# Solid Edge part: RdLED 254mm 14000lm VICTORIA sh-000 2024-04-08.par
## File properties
Author: robert.pupel
Template: iso metric part.par
Last saved by: robert.pupel
Revision: 3
Application: Solid Edge
Gęstość: 0.000 kg/m^3
Dokładność: 0.990
Username: robert.pupel
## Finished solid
Body 1: solid body, 5714 faces, 14913 edges, 9879 vertices.
  Faces by surface: plane 5459, cylinder 126, torus 52, cone 44, spline 23, sphere 10
  Edges by curve: line 14360, curve on surface 311, circle 145, ellipse 66, spline 31
Bounding box of the edges (mm; curved faces can reach further): 254.000 x 4.950 x 254.000, from (-127, -3.45, -127) to (127, 1.5, 127).
Cylindrical faces by radius (mm): R0.199 x1, R0.2 x39, R0.2002 x2, R0.2169 x3, R0.25 x12, R0.3 x2, R0.3373 x3, R0.4 x8, R0.4006 x2, R0.4008 x2, R0.525 x2, R0.6 x12, R1 x7, R1.0894 x2, R1.0991 x4, R1.1 x14, R1.6 x3, R1.65 x3, R5 x4, R127 x1
Conical faces (half-angle, radius in mm at the cone's reference point): 0.3913 deg R1.0968 x2, 0.447 deg R1.0952 x2, 0.464 deg R1.0955 x2, 0.5 deg R0.5056 x4, 0.5 deg R1.0082 x4, 1 deg R0.5511 x2, 10 deg R0.2132 x2, 10 deg R0.4132 x2, 15.6748 deg R1.1041 x1, 15.6751 deg R1.1041 x1, 15.7937 deg R1.1267 x1, 15.7938 deg R1.1267 x1, 18.4844 deg R1.0657 x4, 18.9316 deg R0.5099 x2, 19.4337 deg R0.5111 x2, 27.363 deg R0.6214 x2, 40.1968 deg R0.519 x1, 40.228 deg R0.5176 x1, 42.9179 deg R0.4919 x1, 42.9331 deg R0.4916 x1, 45 deg R0.575 x2, 45 deg R0.625 x4
Toroidal faces (ring radius, tube radius in mm): R0.0958 r0.3997 x4, R0.1 r0.2 x1, R0.1075 r0.4 x2, R0.1101 r0.4001 x2, R0.1216 r0.4 x2, R0.1234 r0.4 x2, R0.1634 r0.2287 x1, R0.1641 r0.2287 x1, R0.3286 r0.2001 x1, R0.3702 r0.4 x2, R0.3818 r0.2 x2, R0.4163 r0.3984 x2, R0.4824 r0.2001 x1, R0.4952 r0.2 x1, R0.6008 r0.3968 x2, R0.6009 r0.3969 x2, R0.6227 r0.2 x1, R0.6235 r0.2 x1, R0.8 r0.2 x4, R0.8522 r0.3 x2, R0.9002 r0.2 x1, R0.9018 r0.2 x1, R0.9181 r0.2227 x2, R0.9197 r0.223 x1, R0.9199 r0.223 x1, R0.9663 r0.2263 x1, R0.9665 r0.2263 x1, R1.3 r0.2 x2, R1.327 r1.1 x2, R1.3271 r1.1 x2, R1.8741 r0.2175 x1, R1.8987 r0.2 x1
Spherical faces by radius (mm): R0.2 x8, R0.6 x2
Planar faces by outward normal: +x 652, +y 8, +z 658, -x 652, -y 1028, -z 649, oblique 1812
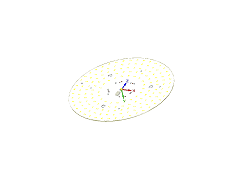
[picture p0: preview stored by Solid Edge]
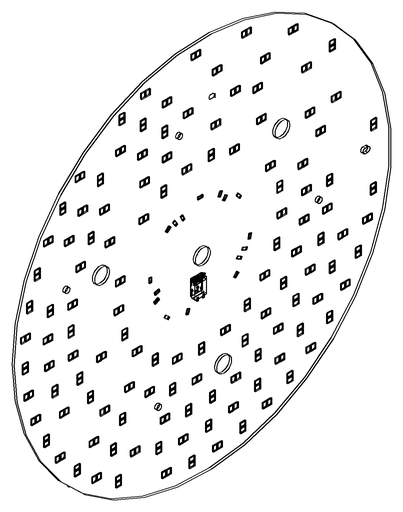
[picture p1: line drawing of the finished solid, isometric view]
